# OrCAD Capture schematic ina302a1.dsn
size A; title: INA293 40-V High-Voltage, High Bandwidth, Unidirectional, 110-V Common-Mode Current-Sense Amplifier; rev: A; note: SBOS870
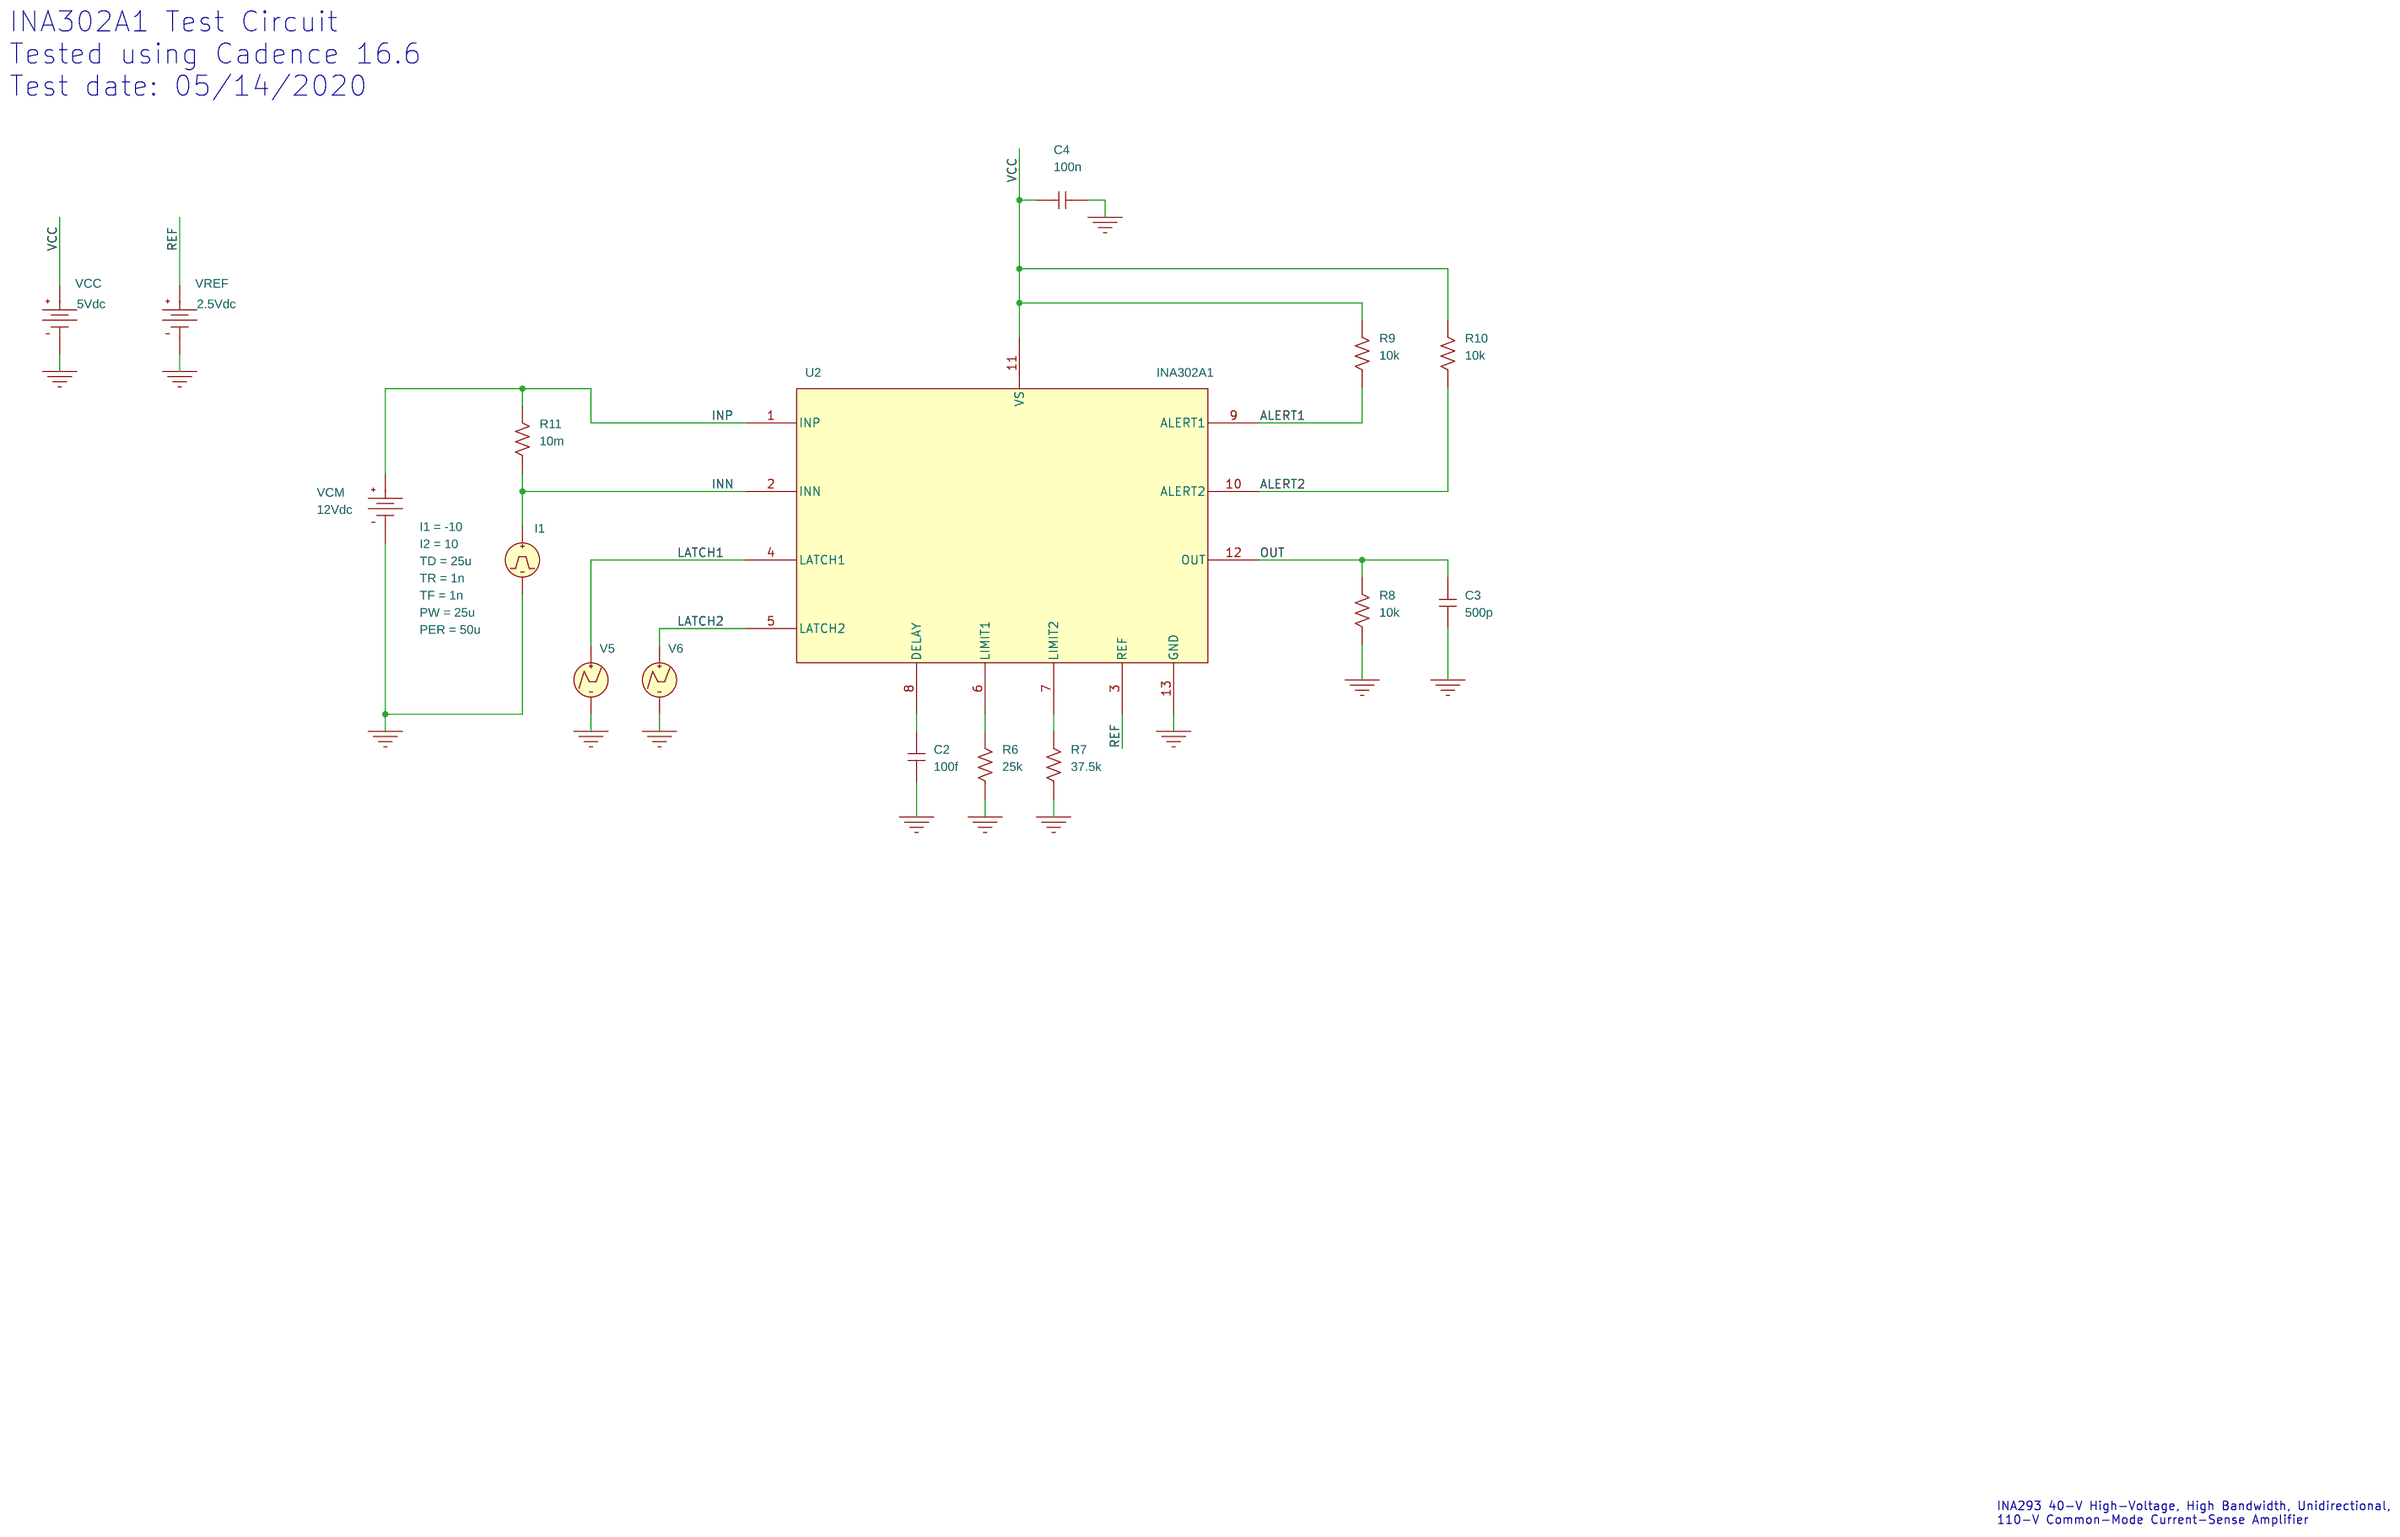
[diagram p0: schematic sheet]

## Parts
C2  100f  [RAD/CK05]
C3  500p  [RAD/CK05]
C4  100n  [RAD/CK05]
I1  IPULSE
R6  25k  [AX/RC05]
R7  37.5k  [AX/RC05]
R8  10k  [AX/RC05]
R9  10k  [AX/RC05]
R10  10k  [AX/RC05]
R11  10m  [AX/RC05]
U2  INA302A1
V5  VPWL
V6  VPWL
VCC  VDC
VCM  VDC
VREF  VDC

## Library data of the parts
C2-C4 = C
I1 = IPULSE: I1: -10; I2: 10; PER: 50u; PW: 25u; TD: 25u; TF: 1n; TR: 1n
R6-R11 = R
U2 = INA302A1
V5 = VPWL: T1: 0; T2: 5m; T3: 5.000001m; T4: 9.5m; T5: 9.500001m; V1: 0; V2: 0; V3: 5; V4: 5; V5: 0
V6 = VPWL: T1: 0; T2: 13m; T3: 13.000001m; T4: 18.5m; T5: 18.500001m; V1: 0; V2: 0; V3: 5; V4: 5; V5: 0
VCC = VDC: DC: 5Vdc
VCM = VDC: DC: 12Vdc
VREF = VDC: DC: 2.5Vdc

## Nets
VCC: C4.2 R9.2 R10.2 U2.11(VS) VCC.0(+)
0: C2.1 C3.1 C4.1 I1.2(-) R6.1 R7.1 R8.1 U2.13(GND) V5.2(-) V6.2(-) VCC.1(-) VCM.1(-) VREF.1(-)
ALERT1: R9.1 U2.9(ALERT1)
ALERT2: R10.1 U2.10(ALERT2)
INN: I1.1(+) R11.1 U2.2(INN)
INP: R11.2 U2.1(INP) VCM.0(+)
LATCH1: U2.4(LATCH1) V5.1(+)
LATCH2: U2.5(LATCH2) V6.1(+)
OUT: C3.2 R8.2 U2.12(OUT)
REF: U2.3(REF) VREF.0(+)
N22835: C2.2 U2.8(DELAY)
N22917: R7.2 U2.7(LIMIT2)
N22923: R6.2 U2.6(LIMIT1)

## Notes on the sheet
- INA302A1 Test Circuit
  Tested using Cadence 16.6
  Test date: 05/14/2020
- INA293 40-V High-Voltage, High Bandwidth, Unidirectional,
  110-V Common-Mode Current-Sense Amplifier
